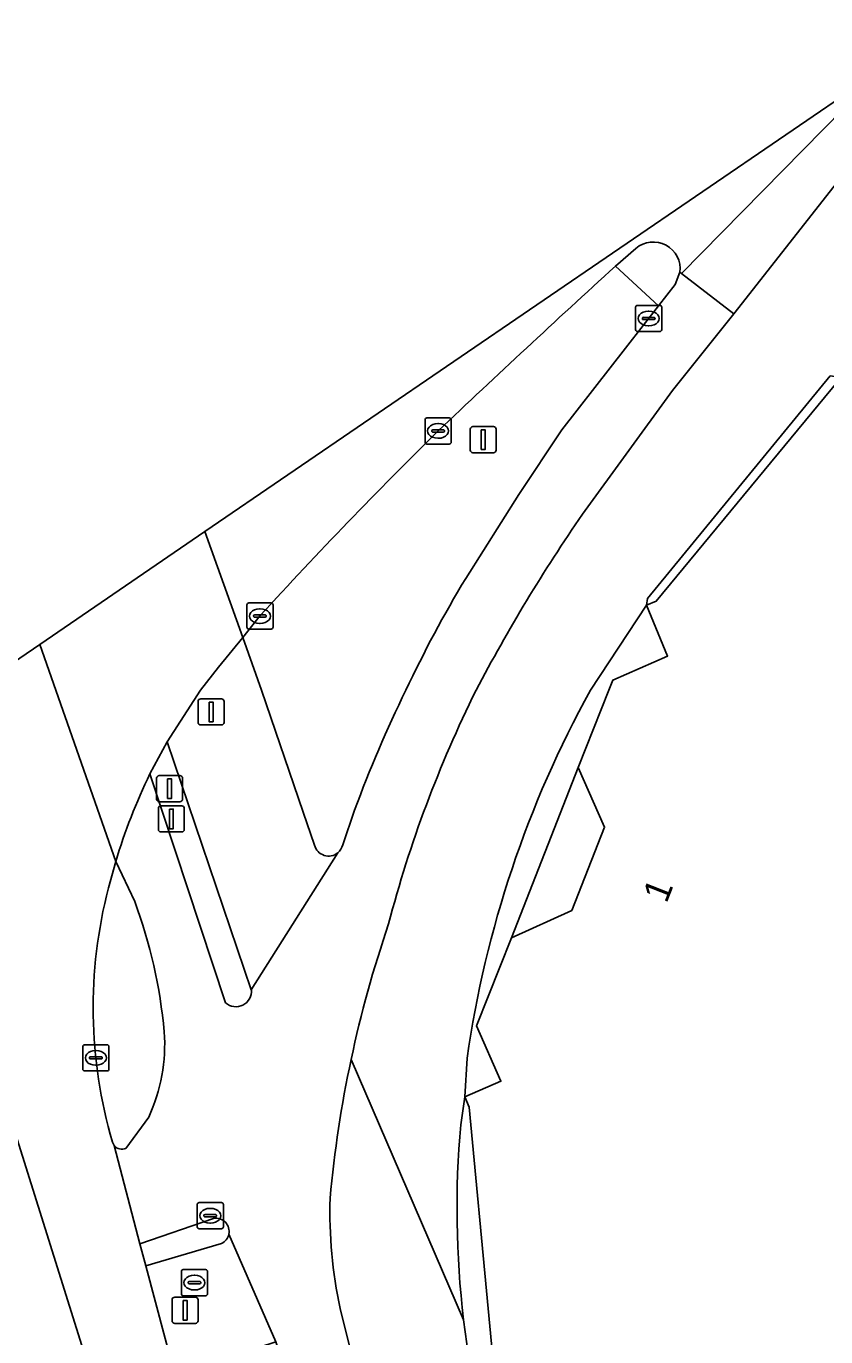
# Model space of a CAD drawing. Extents: x 159499 to 160349, y 382524 to 383273.
# Drawn here: x 159520.1 to 159550.6, y 382975.3 to 383025.4 of the extents above; entities that cross this region are included whole.
import ezdxf

# ---------------------------------------------------------------- set-up
doc = ezdxf.new("R2010")
doc.units = 0
for name, color, linetype in [('IMGEO_Drukknoppaal', 7, 'Continuous'), ('IMGEO_Fietspad_gesloten', 7, 'Continuous'), ('IMGEO_Fietspad_open', 7, 'Continuous'), ('IMGEO_Kolk', 7, 'Continuous'), ('IMGEO_Lichtmast', 7, 'Continuous'), ('IMGEO_Pand', 7, 'Continuous'), ('IMGEO_Pand_nummerreeks', 7, 'Continuous'), ('IMGEO_Rijbaan_lokaal_gesloten', 7, 'Continuous'), ('IMGEO_Rijbaan_regionaal_gesloten', 7, 'Continuous'), ('IMGEO_Rioolput', 7, 'Continuous'), ('IMGEO_Verkeerseiland_open', 7, 'Continuous'), ('IMGEO_Verkeersregelinstallatiepaal', 7, 'Continuous'), ('IMGEO_Voetpad_open', 7, 'Continuous')]:
    doc.layers.add(name, color=color, linetype=linetype)

msp = doc.modelspace()

# ---------------------------------------------------------------- linework, layer by layer
at = {"layer": 'IMGEO_Drukknoppaal'}
for p, q in [((159525.208, 382995.583), (159525.998, 382995.583)), ((159525.998, 382995.583), (159525.208, 382995.583)), ((159525.108, 382994.683), (159525.108, 382995.483)), ((159525.108, 382995.483), (159525.108, 382994.683)), ((159526.098, 382995.483), (159526.098, 382994.683)), ((159526.098, 382994.683), (159526.098, 382995.483)), ((159525.998, 382994.583), (159525.208, 382994.583)), ((159525.208, 382994.583), (159525.998, 382994.583))]:
    msp.add_line(p, q, dxfattribs=at)
msp.add_lwpolyline([(159525.528, 382995.458), (159525.678, 382995.458), (159525.678, 382994.708), (159525.528, 382994.708), (159525.528, 382995.458)], dxfattribs=at)
for centre, start, end in [((159525.208, 382995.483), 90, 180), ((159525.208, 382995.483), 90, 180), ((159525.998, 382995.483), 0, 90), ((159525.998, 382995.483), 360, 90), ((159525.208, 382994.683), 180, 270), ((159525.208, 382994.683), 180, 270), ((159525.998, 382994.683), 270, 0), ((159525.998, 382994.683), 270, 0)]:
    msp.add_arc(centre, 0.1, start, end, dxfattribs=at)
at = {"layer": 'IMGEO_Fietspad_gesloten'}
msp.add_lwpolyline([(159552.836, 383023.807), (159545.093, 383015.936), (159547.092, 383014.399), (159551.764, 383020.344)], dxfattribs=at)
at = {"layer": 'IMGEO_Fietspad_open'}
for points in [[(159541.309, 383006.73), (159544.745, 383011.458), (159547.092, 383014.399), (159545.093, 383015.936), (159545.031, 383015.983), (159544.844, 383015.51), (159544.217, 383014.704), (159540.518, 383009.96), (159538.876, 383007.487), (159536.848, 383004.279)], [(159527.67, 382988.048), (159524.787, 382996.802)], [(159532.604, 382995.417), (159532.149, 382994.086)], [(159531.961, 382993.789), (159528.658, 382988.552)], [(159523.481, 382993.453), (159524.203, 382991.927)], [(159524.737, 382983.678), (159523.867, 382982.482)], [(159523.415, 382982.593), (159524.395, 382978.841), (159527.213, 382979.805)], [(159527.798, 382979.205), (159529.596, 382975.094), (159535.904, 382955.29), (159538.071, 382948.551), (159539.891, 382942.783), (159540.08, 382942.127), (159544.665, 382928.357)], [(159543.818, 382927.718), (159544.222, 382927.182), (159550.079, 382919.415), (159547.321, 382928.042), (159538.641, 382955.193), (159537.218, 382959.569), (159535.582, 382964.78), (159533.952, 382969.832), (159532.765, 382973.478), (159532.054, 382976.364)]]:
    msp.add_lwpolyline(points, dxfattribs=at)
for centre, radius, start, end in [((159594.239, 382970.175), 64.326, 145.37028, 152.37725), ((159577.254, 382979.942), 47.169, 148.9395, 154.835), ((159577.346, 382979.011), 47.655, 153.869, 159.8637), ((159579.049, 382979.261), 46.666, 153.6142, 165.3482), ((159543.862, 382987.434), 21.252, 153.8443, 163.5474), ((159531.61, 382994.219), 0.555, 309.2005, 346.1321), ((159505.943, 382985.173), 19.469, 5.2274, 20.2975), ((159576.679, 382976.461), 45.202, 161.1505, 167.9612), ((159528.064, 382988.497), 0.597, 228.7347, 5.3195), ((159518.653, 382986.472), 6.695, 335.334, 4.0687), ((159576.39, 382976.531), 44.905, 167.9715, 174.8266), ((159523.721, 382982.865), 0.41, 221.5858, 290.8195), ((159548.886, 382980.031), 17.227, 178.1728, 192.2896), ((159527.304, 382979.308), 0.505, 348.206, 100.3435)]:
    msp.add_arc(centre, radius, start, end, dxfattribs=at)
at = {"layer": 'IMGEO_Kolk'}
for p, q in [((159543.336, 383013.791), (159543.336, 383014.643)), ((159543.411, 383014.717), (159544.263, 383014.717)), ((159544.337, 383014.643), (159544.337, 383013.791)), ((159543.595, 383014.211), (159543.595, 383014.223)), ((159544.033, 383014.174), (159543.635, 383014.174)), ((159543.638, 383014.26), (159544.036, 383014.26)), ((159543.824, 383014.497), (159543.849, 383014.497)), ((159544.079, 383014.223), (159544.079, 383014.211)), ((159544.263, 383013.717), (159543.411, 383013.717)), ((159543.847, 383013.937), (159543.822, 383013.937)), ((159535.293, 383009.491), (159535.293, 383010.343)), ((159535.368, 383010.417), (159536.22, 383010.417)), ((159535.781, 383010.197), (159535.806, 383010.197)), ((159536.294, 383010.343), (159536.294, 383009.491)), ((159535.552, 383009.911), (159535.552, 383009.923)), ((159535.99, 383009.874), (159535.592, 383009.874)), ((159535.595, 383009.96), (159535.993, 383009.96)), ((159535.804, 383009.637), (159535.779, 383009.637)), ((159536.036, 383009.923), (159536.036, 383009.911)), ((159536.22, 383009.417), (159535.368, 383009.417)), ((159528.487, 383002.412), (159528.487, 383003.264)), ((159528.562, 383003.338), (159529.414, 383003.338)), ((159528.975, 383003.118), (159529, 383003.118)), ((159529.488, 383003.264), (159529.488, 383002.412)), ((159528.746, 383002.832), (159528.746, 383002.844)), ((159529.184, 383002.795), (159528.786, 383002.795)), ((159528.789, 383002.881), (159529.187, 383002.881)), ((159529.23, 383002.844), (159529.23, 383002.832)), ((159529.414, 383002.338), (159528.562, 383002.338)), ((159528.998, 383002.558), (159528.973, 383002.558)), ((159522.218, 382985.521), (159522.218, 382986.373)), ((159522.293, 382986.447), (159523.145, 382986.447)), ((159522.706, 382986.227), (159522.731, 382986.227)), ((159523.219, 382986.373), (159523.219, 382985.521)), ((159522.477, 382985.941), (159522.477, 382985.953)), ((159522.915, 382985.904), (159522.517, 382985.904)), ((159522.52, 382985.99), (159522.918, 382985.99)), ((159522.729, 382985.667), (159522.704, 382985.667)), ((159522.961, 382985.953), (159522.961, 382985.941)), ((159523.145, 382985.447), (159522.293, 382985.447)), ((159526.588, 382979.486), (159526.588, 382980.338)), ((159526.663, 382980.412), (159527.515, 382980.412)), ((159527.076, 382980.192), (159527.101, 382980.192)), ((159527.589, 382980.338), (159527.589, 382979.486)), ((159526.847, 382979.906), (159526.847, 382979.918)), ((159527.285, 382979.869), (159526.887, 382979.869)), ((159526.89, 382979.955), (159527.288, 382979.955)), ((159527.099, 382979.632), (159527.074, 382979.632)), ((159527.331, 382979.918), (159527.331, 382979.906)), ((159527.515, 382979.412), (159526.663, 382979.412))]:
    msp.add_line(p, q, dxfattribs=at)
for points in [[(159543.336, 383013.791), (159543.336, 383014.643)], [(159543.411, 383014.717), (159544.263, 383014.717)], [(159544.337, 383014.643), (159544.337, 383013.791)], [(159544.263, 383013.717), (159543.411, 383013.717)], [(159535.293, 383009.491), (159535.293, 383010.343)], [(159535.368, 383010.417), (159536.22, 383010.417)], [(159536.294, 383010.343), (159536.294, 383009.491)], [(159536.22, 383009.417), (159535.368, 383009.417)], [(159528.487, 383002.412), (159528.487, 383003.264)], [(159528.562, 383003.338), (159529.414, 383003.338)], [(159529.488, 383003.264), (159529.488, 383002.412)], [(159529.414, 383002.338), (159528.562, 383002.338)], [(159522.218, 382985.521), (159522.218, 382986.373)], [(159522.293, 382986.447), (159523.145, 382986.447)], [(159523.219, 382986.373), (159523.219, 382985.521)], [(159523.145, 382985.447), (159522.293, 382985.447)], [(159526.588, 382979.486), (159526.588, 382980.338)], [(159526.663, 382980.412), (159527.515, 382980.412)], [(159527.589, 382980.338), (159527.589, 382979.486)], [(159527.515, 382979.412), (159526.663, 382979.412)]]:
    msp.add_lwpolyline(points, dxfattribs=at)
for centre, radius, start, end in [((159543.413, 383014.641), 0.0765, 91.552, 178.448), ((159543.413, 383014.641), 0.0765, 91.552, 178.448), ((159544.261, 383014.641), 0.0765, 1.552, 88.448), ((159544.261, 383014.641), 0.0765, 1.552, 88.448), ((159543.635, 383014.22), 0.0403, 85.8775, 175.7526), ((159543.632, 383014.21), 0.0366, 178.938, 274.7102), ((159544.036, 383014.217), 0.043, 264.8664, 352.4533), ((159544.04, 383014.222), 0.0386, 1.7309, 96.639), ((159543.413, 383013.793), 0.0765, 181.552, 268.448), ((159543.413, 383013.793), 0.0765, 181.552, 268.448), ((159544.261, 383013.793), 0.0765, 271.552, 358.448), ((159544.261, 383013.793), 0.0765, 271.552, 358.448), ((159535.37, 383010.341), 0.0765, 91.552, 178.448), ((159535.37, 383010.341), 0.0765, 91.552, 178.448), ((159536.218, 383010.341), 0.0765, 1.552, 88.448), ((159536.218, 383010.341), 0.0765, 1.552, 88.448), ((159535.592, 383009.92), 0.0403, 85.8775, 175.7526), ((159535.589, 383009.91), 0.0366, 178.938, 274.7102), ((159535.993, 383009.917), 0.043, 264.8664, 352.4533), ((159535.997, 383009.922), 0.0386, 1.7309, 96.639), ((159535.37, 383009.493), 0.0765, 181.552, 268.448), ((159535.37, 383009.493), 0.0765, 181.552, 268.448), ((159536.218, 383009.493), 0.0765, 271.552, 358.448), ((159536.218, 383009.493), 0.0765, 271.552, 358.448), ((159528.564, 383003.262), 0.0765, 91.552, 178.448), ((159528.564, 383003.262), 0.0765, 91.552, 178.448), ((159529.412, 383003.262), 0.0765, 1.552, 88.448), ((159529.412, 383003.262), 0.0765, 1.552, 88.448), ((159528.786, 383002.841), 0.0403, 85.8775, 175.7526), ((159528.783, 383002.831), 0.0366, 178.938, 274.7102), ((159529.187, 383002.838), 0.043, 264.8664, 352.4533), ((159529.191, 383002.843), 0.0386, 1.7309, 96.639), ((159528.564, 383002.414), 0.0765, 181.552, 268.448), ((159528.564, 383002.414), 0.0765, 181.552, 268.448), ((159529.412, 383002.414), 0.0765, 271.552, 358.448), ((159529.412, 383002.414), 0.0765, 271.552, 358.448), ((159522.295, 382986.371), 0.0765, 91.552, 178.448), ((159522.295, 382986.371), 0.0765, 91.552, 178.448), ((159523.143, 382986.371), 0.0765, 1.552, 88.448), ((159523.143, 382986.371), 0.0765, 1.552, 88.448), ((159522.517, 382985.95), 0.0403, 85.8775, 175.7526), ((159522.514, 382985.94), 0.0366, 178.938, 274.7102), ((159522.918, 382985.947), 0.043, 264.8664, 352.4533), ((159522.922, 382985.952), 0.0386, 1.7309, 96.639), ((159522.295, 382985.523), 0.0765, 181.552, 268.448), ((159522.295, 382985.523), 0.0765, 181.552, 268.448), ((159523.143, 382985.523), 0.0765, 271.552, 358.448), ((159523.143, 382985.523), 0.0765, 271.552, 358.448), ((159526.665, 382980.336), 0.0765, 91.552, 178.448), ((159526.665, 382980.336), 0.0765, 91.552, 178.448), ((159527.513, 382980.336), 0.0765, 1.552, 88.448), ((159527.513, 382980.336), 0.0765, 1.552, 88.448), ((159526.887, 382979.915), 0.0403, 85.8775, 175.7526), ((159526.884, 382979.905), 0.0366, 178.938, 274.7102), ((159527.288, 382979.912), 0.043, 264.8664, 352.4533), ((159527.292, 382979.917), 0.0386, 1.7309, 96.639), ((159526.665, 382979.488), 0.0765, 181.552, 268.448), ((159526.665, 382979.488), 0.0765, 181.552, 268.448), ((159527.513, 382979.488), 0.0765, 271.552, 358.448), ((159527.513, 382979.488), 0.0765, 271.552, 358.448)]:
    msp.add_arc(centre, radius, start, end, dxfattribs=at)
for centre, major_axis, ratio, start_param, end_param in [((159543.823, 383014.217), (-0.387, 0.002), 0.722429, 4.712389, 7.853982), ((159543.848, 383014.217), (-0.39, 0.002), 0.717154, 1.570796, 4.712389), ((159535.78, 383009.917), (-0.387, 0.002), 0.722429, 4.712389, 7.853982), ((159535.805, 383009.917), (-0.39, 0.002), 0.717154, 1.570796, 4.712389), ((159528.974, 383002.838), (-0.387, 0.002), 0.722429, 4.712389, 7.853982), ((159528.999, 383002.838), (-0.39, 0.002), 0.717154, 1.570796, 4.712389), ((159522.705, 382985.947), (-0.387, 0.002), 0.722429, 4.712389, 7.853982), ((159522.73, 382985.947), (-0.39, 0.002), 0.717154, 1.570796, 4.712389), ((159527.075, 382979.912), (-0.387, 0.002), 0.722429, 4.712389, 7.853982), ((159527.1, 382979.912), (-0.39, 0.002), 0.717154, 1.570796, 4.712389)]:
    msp.add_ellipse(centre, major_axis=major_axis, ratio=ratio, start_param=start_param, end_param=end_param, dxfattribs=at)
at = {"layer": 'IMGEO_Lichtmast'}
for p, q in [((159537.022, 383009.182), (159537.022, 383009.982)), ((159537.022, 383009.982), (159537.022, 383009.182)), ((159537.122, 383010.082), (159537.912, 383010.082)), ((159537.912, 383010.082), (159537.122, 383010.082)), ((159538.012, 383009.982), (159538.012, 383009.182)), ((159538.012, 383009.182), (159538.012, 383009.982)), ((159537.912, 383009.082), (159537.122, 383009.082)), ((159537.122, 383009.082), (159537.912, 383009.082))]:
    msp.add_line(p, q, dxfattribs=at)
msp.add_lwpolyline([(159537.442, 383009.957), (159537.592, 383009.957), (159537.592, 383009.207), (159537.442, 383009.207), (159537.442, 383009.957)], dxfattribs=at)
for centre, start, end in [((159537.122, 383009.982), 90, 180), ((159537.122, 383009.982), 90, 180), ((159537.912, 383009.982), 0, 90), ((159537.912, 383009.982), 360, 90), ((159537.122, 383009.182), 180, 270), ((159537.122, 383009.182), 180, 270), ((159537.912, 383009.182), 270, 0), ((159537.912, 383009.182), 270, 0)]:
    msp.add_arc(centre, 0.1, start, end, dxfattribs=at)
at = {"layer": 'IMGEO_Pand'}
msp.add_lwpolyline([(159538.52, 382968.383), (159563.21, 382979.1), (159565.208, 382980.005), (159562.875, 382985.371), (159556.514, 383000), (159555.064, 383003.326), (159551.308, 383011.943), (159551.107, 383011.856), (159544.127, 383003.413), (159543.752, 383003.257), (159544.561, 383001.309), (159542.463, 383000.389), (159542.31, 383000), (159541.147, 382997.049), (159542.15, 382994.77), (159540.899, 382991.583), (159538.596, 382990.53), (159537.263, 382987.168), (159538.193, 382985.055), (159536.808, 382984.454), (159536.975, 382984.056), (159538.429, 382968.666)], close=True, dxfattribs=at)
at = {"layer": 'IMGEO_Rijbaan_lokaal_gesloten'}
for points in [[(159552.836, 383023.807), (159552.249, 383023.406), (159526.882, 383006.066), (159528.328, 383002.02), (159528.997, 383002.855)], [(159545.031, 383015.983), (159545.093, 383015.936), (159552.836, 383023.807)], [(159542.564, 383016.217), (159543.344, 383016.896)], [(159526.882, 383006.066), (159520.574, 383001.754), (159520.574, 383001.754), (159523.481, 382993.453)], [(159524.787, 382996.802), (159525.439, 382998.027), (159526.72, 383000), (159527.401, 383000.886), (159528.328, 383002.02), (159526.882, 383006.066)]]:
    msp.add_lwpolyline(points, dxfattribs=at)
for centre, radius, start, end in [((159544.01, 383016.112), 1.029, 352.7847, 130.371), ((159905.36, 382619.568), 537.542, 132.44766, 133.43338), ((159669.072, 382874.838), 189.761, 134.61554, 137.57532), ((159543.862, 382987.434), 21.252, 153.8443, 163.5474)]:
    msp.add_arc(centre, radius, start, end, dxfattribs=at)
at = {"layer": 'IMGEO_Rijbaan_regionaal_gesloten'}
for points in [[(159523.202, 382992.444), (159523.481, 382993.453), (159520.574, 383001.754), (159520.574, 383001.754), (159514.981, 382997.931)], [(159510.149, 382979.571), (159510.695, 382977.599), (159511.604, 382974.413), (159511.637, 382974.298), (159513.016, 382969.443), (159516.385, 382970.606), (159519.416, 382971.652), (159522.84, 382972.833), (159514.981, 382997.931)], [(159514.981, 382997.931), (159522.84, 382972.833), (159525.731, 382973.831), (159524.622, 382977.989), (159524.395, 382978.841), (159523.415, 382982.593), (159523.354, 382982.728)]]:
    msp.add_lwpolyline(points, dxfattribs=at)
msp.add_arc((159540.882, 382987.861), 18.265, 165.4692, 196.3233, dxfattribs=at)
at = {"layer": 'IMGEO_Rioolput'}
for p, q in [((159525.985, 382976.927), (159525.985, 382977.779)), ((159526.06, 382977.853), (159526.912, 382977.853)), ((159526.473, 382977.633), (159526.498, 382977.633)), ((159526.986, 382977.779), (159526.986, 382976.927)), ((159526.244, 382977.347), (159526.244, 382977.359)), ((159526.682, 382977.31), (159526.284, 382977.31)), ((159526.287, 382977.396), (159526.685, 382977.396)), ((159526.496, 382977.073), (159526.471, 382977.073)), ((159526.728, 382977.359), (159526.728, 382977.347)), ((159526.912, 382976.853), (159526.06, 382976.853))]:
    msp.add_line(p, q, dxfattribs=at)
for points in [[(159525.985, 382976.927), (159525.985, 382977.779)], [(159526.06, 382977.853), (159526.912, 382977.853)], [(159526.986, 382977.779), (159526.986, 382976.927)], [(159526.912, 382976.853), (159526.06, 382976.853)]]:
    msp.add_lwpolyline(points, dxfattribs=at)
for centre, radius, start, end in [((159526.062, 382977.777), 0.0765, 91.552, 178.448), ((159526.062, 382977.777), 0.0765, 91.552, 178.448), ((159526.91, 382977.777), 0.0765, 1.552, 88.448), ((159526.91, 382977.777), 0.0765, 1.552, 88.448), ((159526.284, 382977.356), 0.0403, 85.8775, 175.7526), ((159526.281, 382977.346), 0.0366, 178.938, 274.7102), ((159526.685, 382977.353), 0.043, 264.8664, 352.4533), ((159526.689, 382977.358), 0.0386, 1.7309, 96.639), ((159526.062, 382976.929), 0.0765, 181.552, 268.448), ((159526.062, 382976.929), 0.0765, 181.552, 268.448), ((159526.91, 382976.929), 0.0765, 271.552, 358.448), ((159526.91, 382976.929), 0.0765, 271.552, 358.448)]:
    msp.add_arc(centre, radius, start, end, dxfattribs=at)
for centre, major_axis, ratio, start_param, end_param in [((159526.472, 382977.353), (-0.387, 0.002), 0.722429, 4.712389, 7.853982), ((159526.497, 382977.353), (-0.39, 0.002), 0.717154, 1.570796, 4.712389)]:
    msp.add_ellipse(centre, major_axis=major_axis, ratio=ratio, start_param=start_param, end_param=end_param, dxfattribs=at)
at = {"layer": 'IMGEO_Verkeerseiland_open'}
for points in [[(159543.344, 383016.896), (159542.564, 383016.217), (159544.217, 383014.704), (159544.844, 383015.51), (159545.031, 383015.983)], [(159536.848, 383004.279), (159538.876, 383007.487), (159540.518, 383009.96), (159544.217, 383014.704), (159542.564, 383016.217)], [(159528.997, 383002.855), (159528.328, 383002.02), (159529.042, 383000), (159530.639, 382995.347), (159531.072, 382994.078)], [(159528.658, 382988.552), (159525.439, 382998.027), (159524.787, 382996.802), (159527.67, 382988.048)], [(159532.149, 382994.086), (159532.604, 382995.417)], [(159524.203, 382991.927), (159523.481, 382993.453), (159523.202, 382992.444)], [(159523.867, 382982.482), (159524.737, 382983.678)], [(159523.354, 382982.728), (159523.415, 382982.593)], [(159527.213, 382979.805), (159524.395, 382978.841), (159524.622, 382977.989), (159527.517, 382978.85)]]:
    msp.add_lwpolyline(points, dxfattribs=at)
for centre, radius, start, end in [((159544.01, 383016.112), 1.029, 352.7847, 130.371), ((159905.36, 382619.568), 537.542, 132.44766, 133.43338), ((159669.072, 382874.838), 189.761, 134.61554, 137.57532), ((159577.254, 382979.942), 47.169, 148.9395, 154.835), ((159577.346, 382979.011), 47.655, 153.869, 159.8637), ((159531.609, 382994.218), 0.555, 194.6013, 309.3816), ((159531.61, 382994.219), 0.555, 309.2005, 346.1321), ((159540.882, 382987.861), 18.265, 165.4692, 196.3233), ((159505.943, 382985.173), 19.469, 5.2274, 20.2975), ((159528.064, 382988.497), 0.597, 228.7347, 5.3195), ((159518.653, 382986.472), 6.695, 335.334, 4.0687), ((159523.721, 382982.865), 0.41, 221.5858, 290.8195), ((159527.304, 382979.308), 0.505, 348.206, 100.3435), ((159527.307, 382979.305), 0.501, 294.7481, 348.5252)]:
    msp.add_arc(centre, radius, start, end, dxfattribs=at)
at = {"layer": 'IMGEO_Verkeersregelinstallatiepaal'}
for p, q in [((159526.725, 382999.674), (159527.515, 382999.674)), ((159527.515, 382999.674), (159526.725, 382999.674)), ((159526.625, 382998.774), (159526.625, 382999.574)), ((159526.625, 382999.574), (159526.625, 382998.774)), ((159527.615, 382999.574), (159527.615, 382998.774)), ((159527.615, 382998.774), (159527.615, 382999.574)), ((159527.515, 382998.674), (159526.725, 382998.674)), ((159526.725, 382998.674), (159527.515, 382998.674)), ((159525.041, 382995.84), (159525.041, 382996.64)), ((159525.041, 382996.64), (159525.041, 382995.84)), ((159525.141, 382996.74), (159525.931, 382996.74)), ((159525.931, 382996.74), (159525.141, 382996.74)), ((159526.031, 382996.64), (159526.031, 382995.84)), ((159526.031, 382995.84), (159526.031, 382996.64)), ((159525.931, 382995.74), (159525.141, 382995.74)), ((159525.141, 382995.74), (159525.931, 382995.74)), ((159525.632, 382975.895), (159525.632, 382976.695)), ((159525.632, 382976.695), (159525.632, 382975.895)), ((159525.732, 382976.795), (159526.522, 382976.795)), ((159526.522, 382976.795), (159525.732, 382976.795)), ((159526.622, 382976.695), (159526.622, 382975.895)), ((159526.622, 382975.895), (159526.622, 382976.695)), ((159526.522, 382975.795), (159525.732, 382975.795)), ((159525.732, 382975.795), (159526.522, 382975.795))]:
    msp.add_line(p, q, dxfattribs=at)
for points in [[(159527.045, 382999.549), (159527.195, 382999.549), (159527.195, 382998.799), (159527.045, 382998.799), (159527.045, 382999.549)], [(159525.461, 382996.615), (159525.611, 382996.615), (159525.611, 382995.865), (159525.461, 382995.865), (159525.461, 382996.615)], [(159526.052, 382976.67), (159526.202, 382976.67), (159526.202, 382975.92), (159526.052, 382975.92), (159526.052, 382976.67)]]:
    msp.add_lwpolyline(points, dxfattribs=at)
for centre, start, end in [((159526.725, 382999.574), 90, 180), ((159526.725, 382999.574), 90, 180), ((159527.515, 382999.574), 0, 90), ((159527.515, 382999.574), 360, 90), ((159526.725, 382998.774), 180, 270), ((159526.725, 382998.774), 180, 270), ((159527.515, 382998.774), 270, 0), ((159527.515, 382998.774), 270, 0), ((159525.141, 382996.64), 90, 180), ((159525.141, 382996.64), 90, 180), ((159525.931, 382996.64), 0, 90), ((159525.931, 382996.64), 360, 90), ((159525.141, 382995.84), 180, 270), ((159525.141, 382995.84), 180, 270), ((159525.931, 382995.84), 270, 0), ((159525.931, 382995.84), 270, 0), ((159525.732, 382976.695), 90, 180), ((159525.732, 382976.695), 90, 180), ((159526.522, 382976.695), 0, 90), ((159526.522, 382976.695), 360, 90), ((159525.732, 382975.895), 180, 270), ((159525.732, 382975.895), 180, 270), ((159526.522, 382975.895), 270, 0), ((159526.522, 382975.895), 270, 0)]:
    msp.add_arc(centre, 0.1, start, end, dxfattribs=at)
at = {"layer": 'IMGEO_Voetpad_open'}
for points in [[(159541.615, 383000), (159543.752, 383003.257), (159543.789, 383003.505), (159550.776, 383012.021), (159551.308, 383011.943), (159552.985, 383013.033), (159555.492, 383014.686), (159553.53, 383017.705), (159558.995, 383021.203), (159563.163, 383023.911), (159568.383, 383027.302)], [(159552.022, 383018.991), (159551.532, 383019.344), (159552.129, 383020.063), (159551.764, 383020.344), (159547.092, 383014.399), (159544.745, 383011.458), (159541.309, 383006.73)], [(159536.903, 382985.93), (159536.808, 382984.454), (159538.193, 382985.055), (159537.263, 382987.168), (159538.596, 382990.53), (159541.147, 382997.049), (159542.31, 383000), (159542.463, 383000.389), (159544.561, 383001.309), (159543.752, 383003.257), (159541.615, 383000)], [(159531.072, 382994.078), (159530.639, 382995.347), (159529.042, 383000), (159528.328, 383002.02), (159527.401, 383000.886), (159526.72, 383000), (159525.439, 382998.027), (159528.658, 382988.552), (159531.961, 382993.789)], [(159532.471, 382985.889), (159536.769, 382975.935)], [(159536.769, 382975.935), (159532.471, 382985.889)], [(159536.66, 382983.391), (159536.808, 382984.454), (159536.903, 382985.93)], [(159536.975, 382984.056), (159536.808, 382984.454), (159536.66, 382983.391)], [(159538.429, 382968.666), (159536.975, 382984.056)], [(159527.517, 382978.85), (159524.622, 382977.989), (159525.731, 382973.831), (159529.596, 382975.094), (159527.798, 382979.205)], [(159532.054, 382976.364), (159532.765, 382973.478), (159533.952, 382969.832), (159535.582, 382964.78), (159537.218, 382959.569), (159538.641, 382955.193), (159547.321, 382928.042), (159550.079, 382919.415), (159550.348, 382918.574), (159553.201, 382909.181), (159553.741, 382907.489), (159553.797, 382907.263)]]:
    msp.add_lwpolyline(points, dxfattribs=at)
for points in [[(159543.752, 383003.257), (159544.127, 383003.413), (159551.107, 383011.856), (159551.308, 383011.943), (159550.776, 383012.021), (159543.789, 383003.505)], [(159538.596, 382990.53), (159540.899, 382991.583), (159542.15, 382994.77), (159541.147, 382997.049)]]:
    msp.add_lwpolyline(points, close=True, dxfattribs=at)
for centre, radius, start, end in [((159594.239, 382970.175), 64.326, 145.37028, 152.37725), ((159579.049, 382979.261), 46.666, 153.6142, 165.3482), ((159577.483, 382980.164), 40.987, 151.056, 171.913), ((159577.483, 382980.164), 40.987, 151.056, 171.913), ((159531.609, 382994.218), 0.555, 194.6013, 309.3816), ((159576.679, 382976.461), 45.202, 161.1505, 167.9612), ((159576.39, 382976.531), 44.905, 167.9715, 174.8266), ((159572.161, 382980.181), 35.646, 174.8337, 186.8414), ((159572.161, 382980.181), 35.646, 174.8337, 186.8414), ((159548.886, 382980.031), 17.227, 178.1728, 192.2896), ((159527.307, 382979.305), 0.501, 294.7481, 348.5252), ((159572.088, 382980.177), 35.573, 186.8482, 198.8795), ((159572.088, 382980.177), 35.573, 186.8482, 198.8795)]:
    msp.add_arc(centre, radius, start, end, dxfattribs=at)

# ---------------------------------------------------------------- texts
at = {"layer": 'IMGEO_Pand_nummerreeks'}
msp.add_text('1', height=1, rotation=68.5684, dxfattribs=at).set_placement((159544.519, 382991.828))

doc.saveas('drawing.dxf')
